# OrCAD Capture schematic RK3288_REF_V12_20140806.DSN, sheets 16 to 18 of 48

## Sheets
16 32.RAM-DDR3 2x32bit (option): size Custom; title: RAM-DDR3 2x32bit (option); note: RAM-DDR3 2x32bit (option)
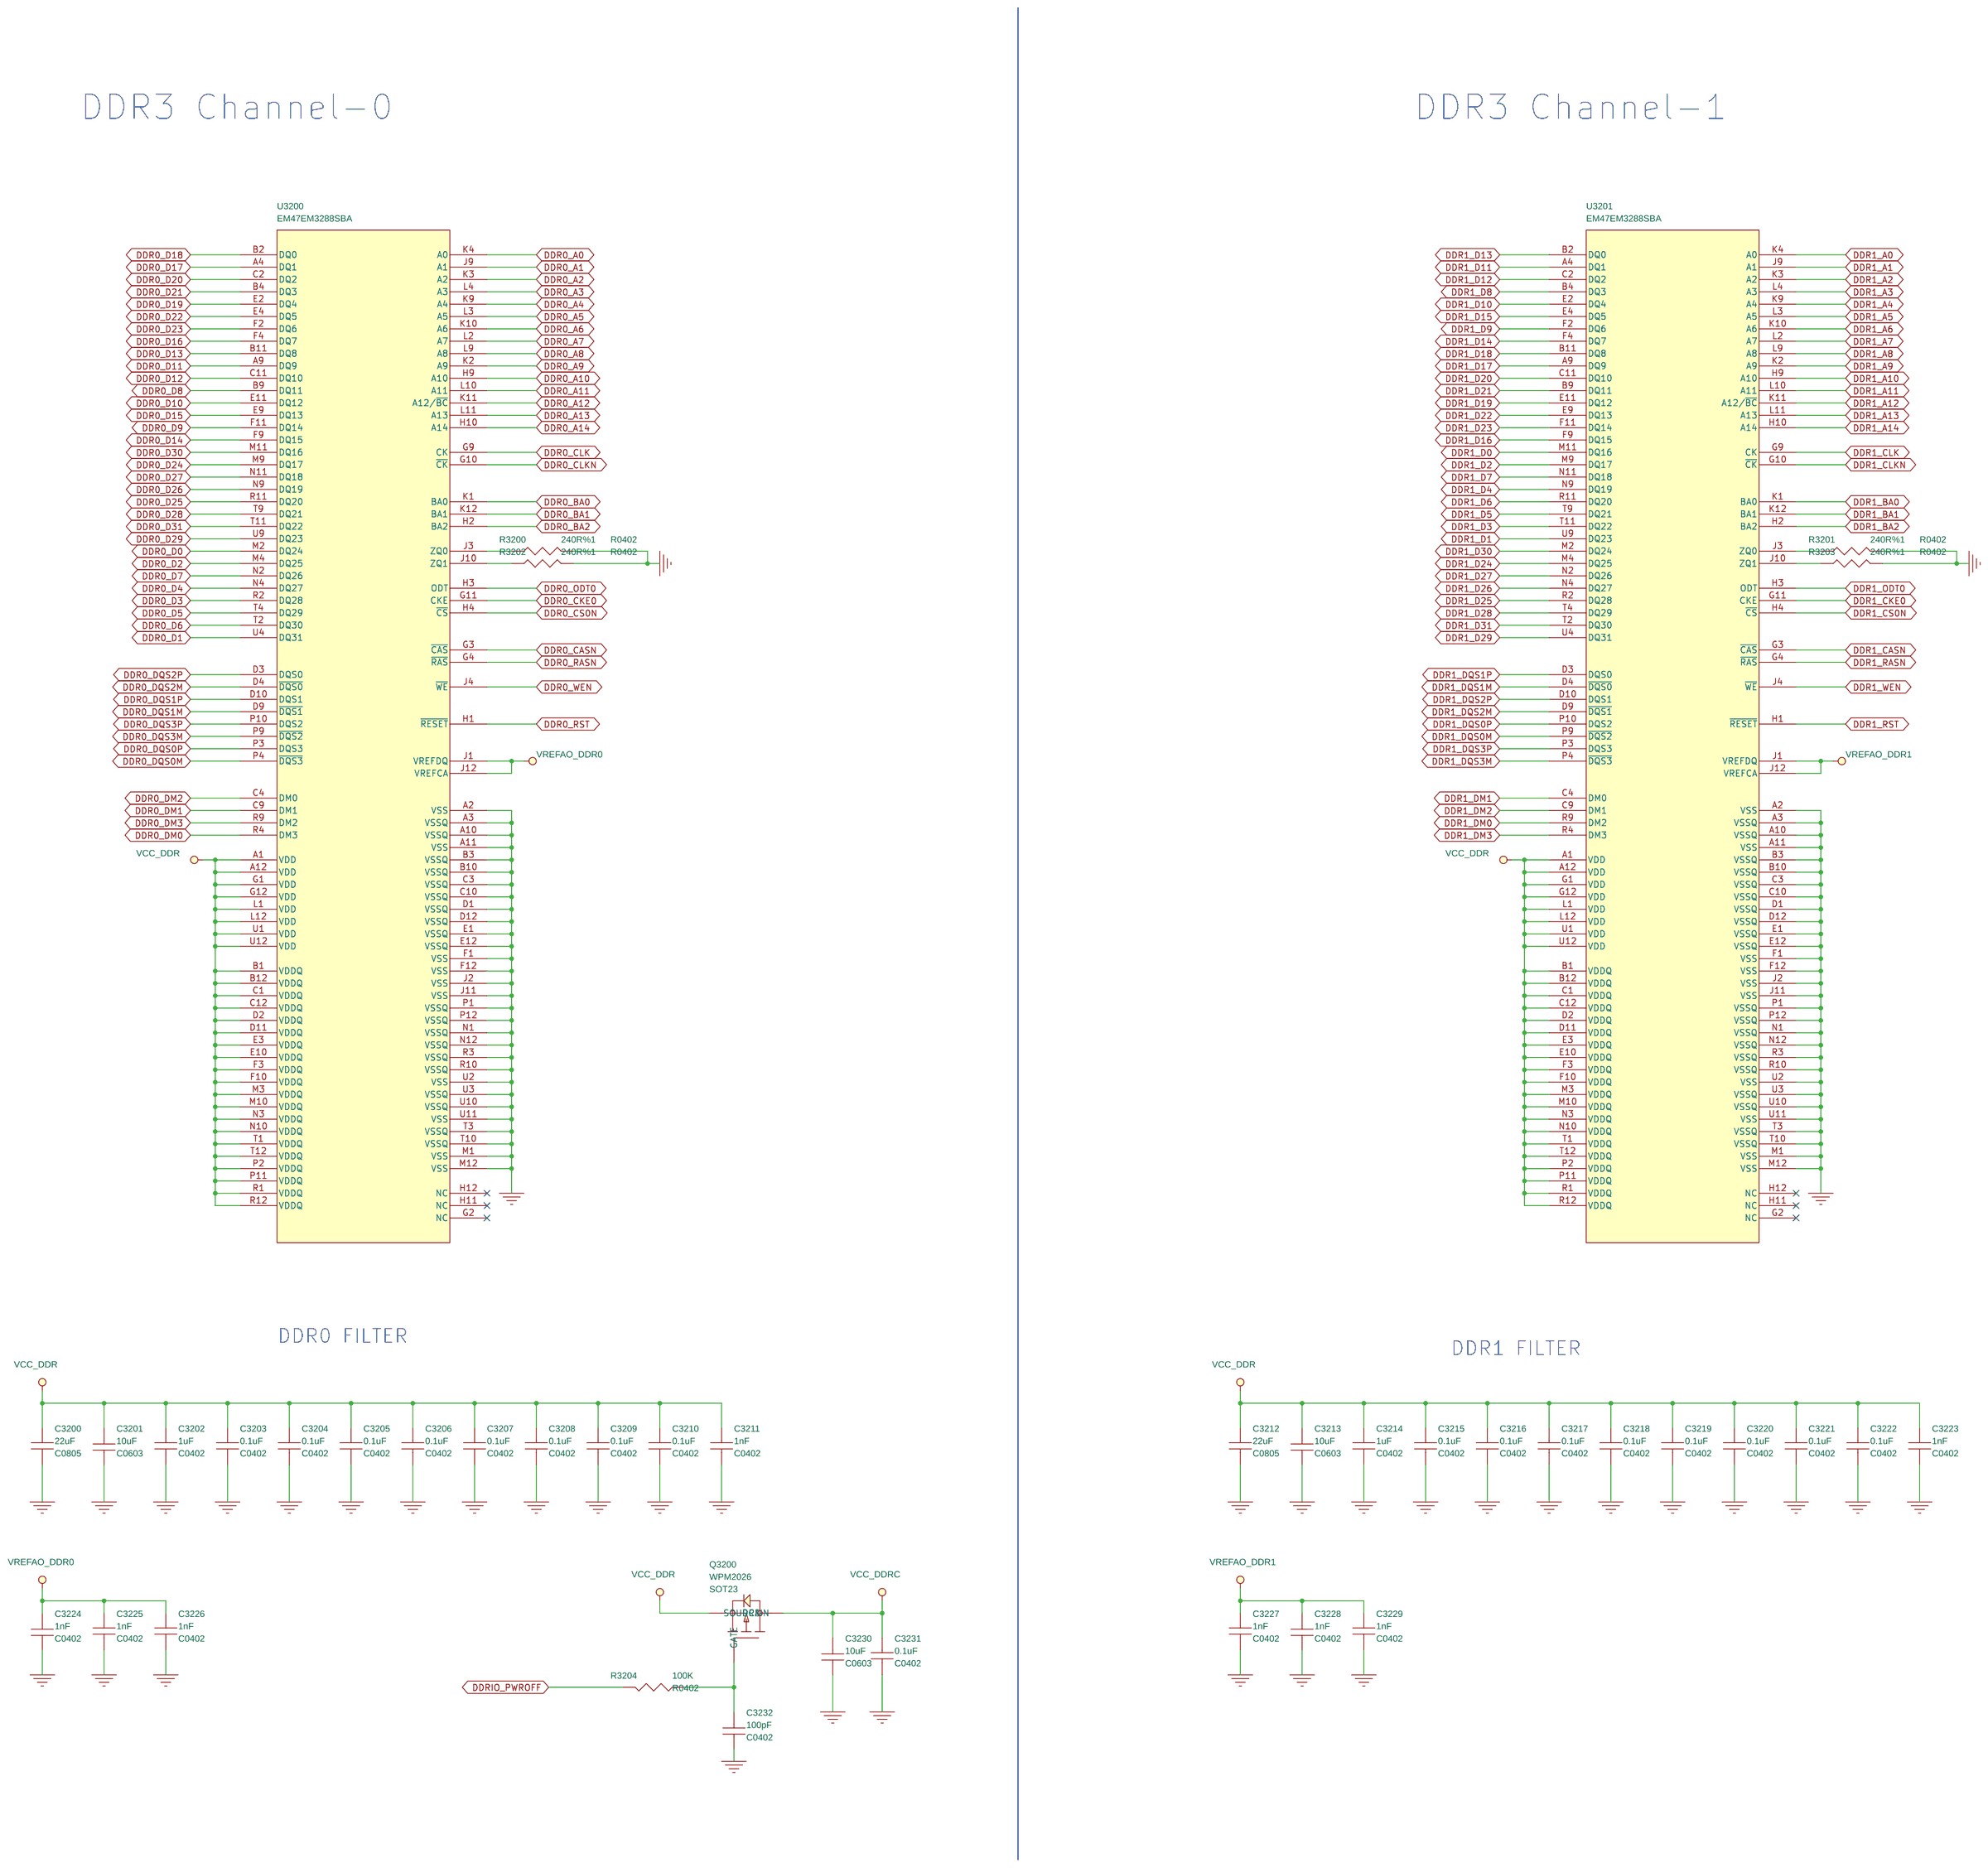
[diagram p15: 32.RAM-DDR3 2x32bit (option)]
17 33.RAM-LPDDR2(168P) (option): size Custom; title: RAM-LPDDR2(168P) (option); note: DDR-LPDDR2(168P) (option)
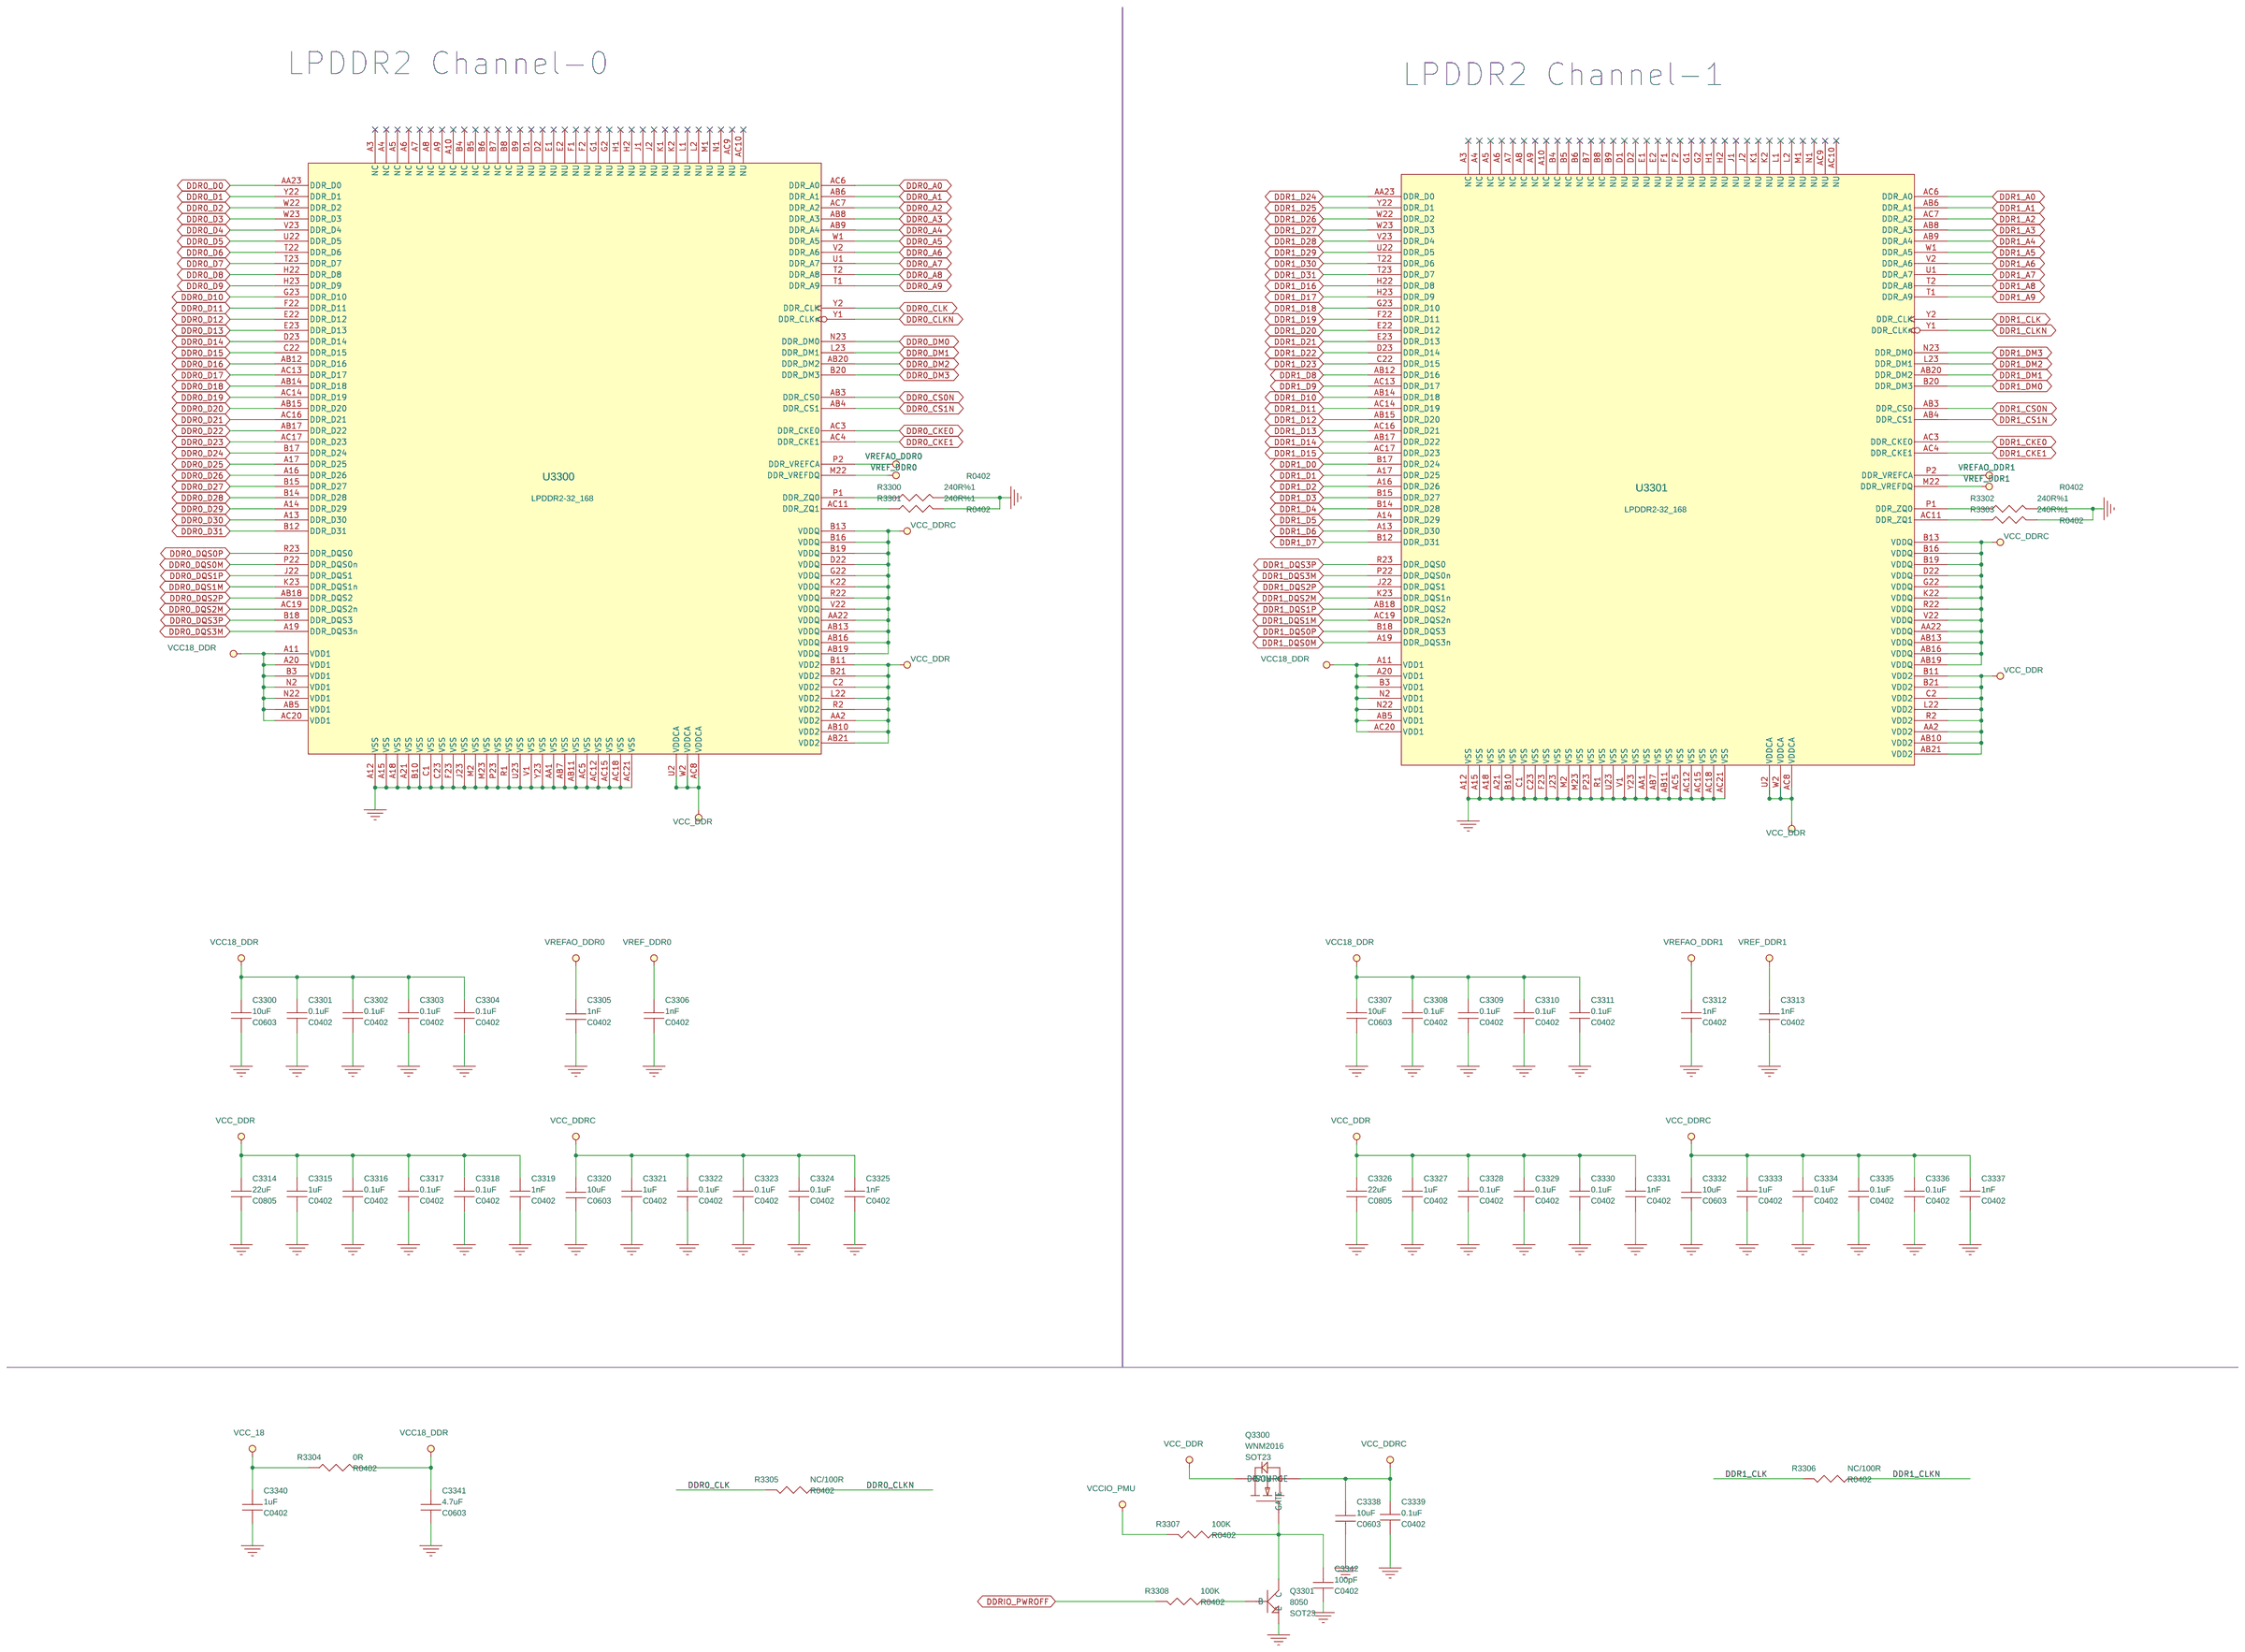
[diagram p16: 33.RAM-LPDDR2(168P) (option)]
18 34.RAM-LPDDR2(216P) (option): size A3; title: RAM-LPDDR2(216P) (option); note: DDR-LPDDR2(220P) (option)
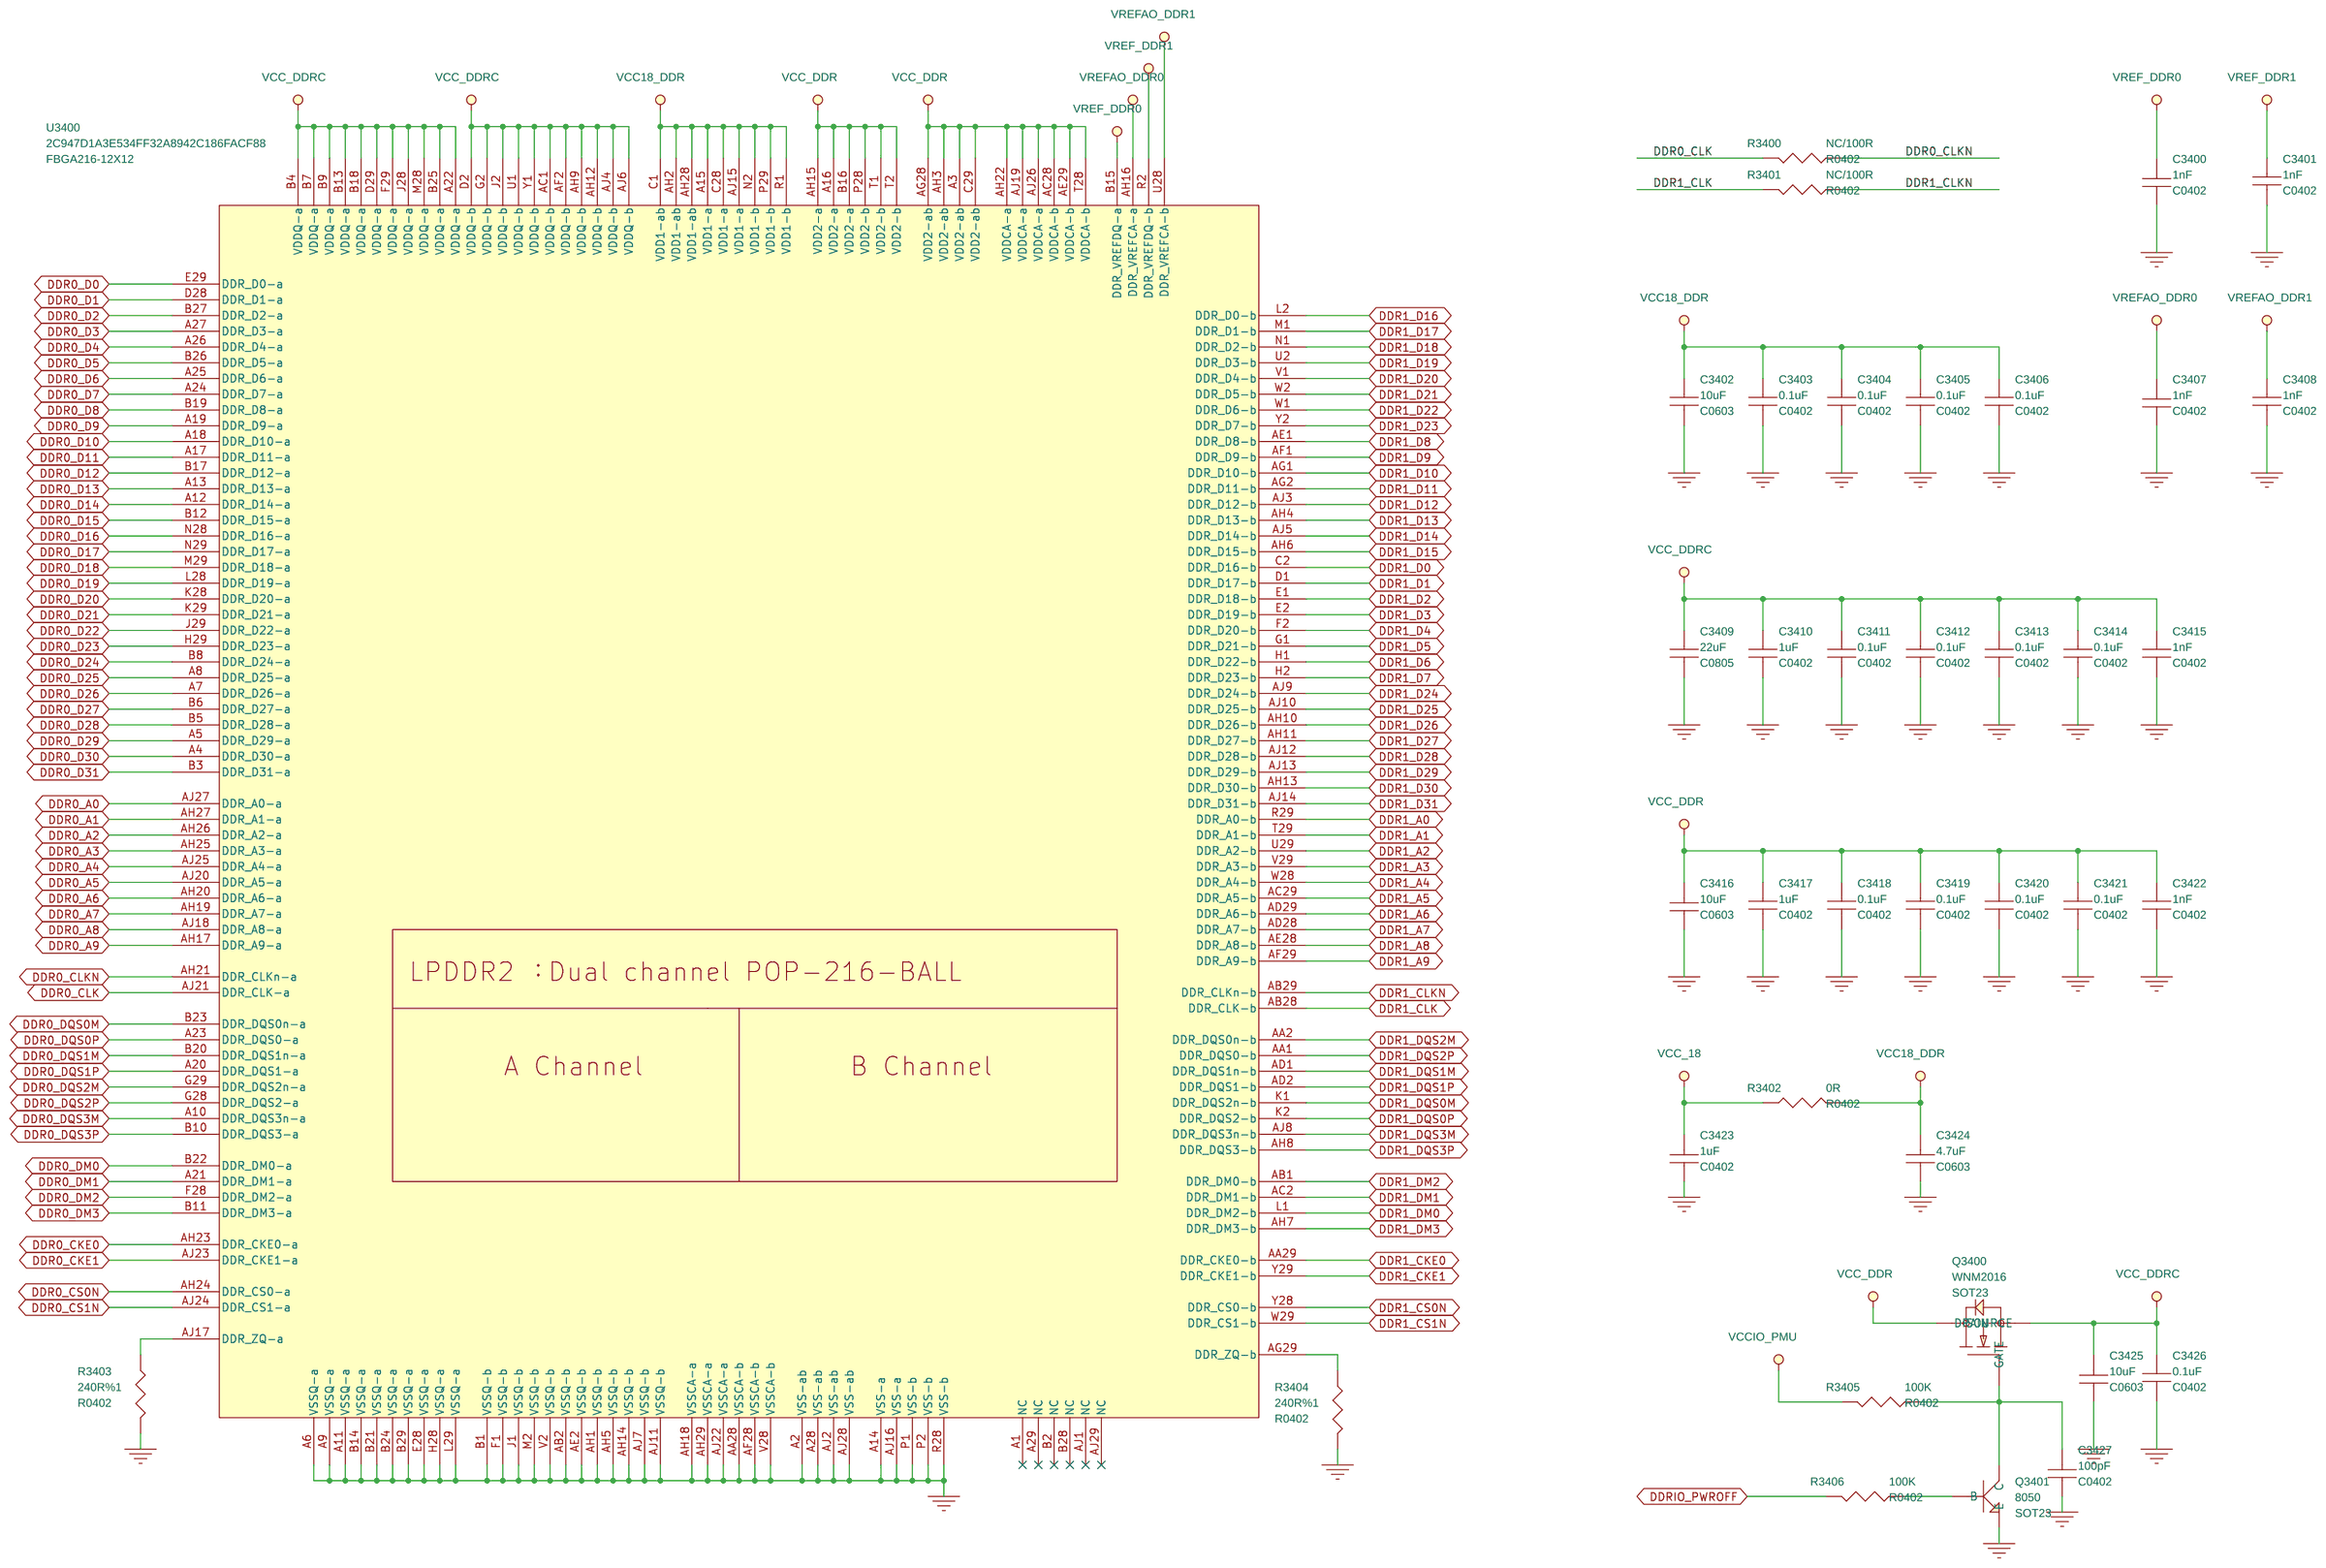
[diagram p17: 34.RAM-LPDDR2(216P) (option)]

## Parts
sheet 32.RAM-DDR3 2x32bit (option)
C3200  22uF  [C0805]
C3201  10uF  [C0603]
C3202  1uF  [C0402]
C3203  0.1uF  [C0402]
C3204  0.1uF  [C0402]
C3205  0.1uF  [C0402]
C3206  0.1uF  [C0402]
C3207  0.1uF  [C0402]
C3208  0.1uF  [C0402]
C3209  0.1uF  [C0402]
C3210  0.1uF  [C0402]
C3211  1nF  [C0402]
C3212  22uF  [C0805]
C3213  10uF  [C0603]
C3214  1uF  [C0402]
C3215  0.1uF  [C0402]
C3216  0.1uF  [C0402]
C3217  0.1uF  [C0402]
C3218  0.1uF  [C0402]
C3219  0.1uF  [C0402]
C3220  0.1uF  [C0402]
C3221  0.1uF  [C0402]
C3222  0.1uF  [C0402]
C3223  1nF  [C0402]
C3224  1nF  [C0402]
C3225  1nF  [C0402]
C3226  1nF  [C0402]
C3227  1nF  [C0402]
C3228  1nF  [C0402]
C3229  1nF  [C0402]
C3230  10uF  [C0603]
C3231  0.1uF  [C0402]
C3232  100pF  [C0402]
Q3200  WPM2026  [SOT23]
R3200  240R%1  [R0402]
R3201  240R%1  [R0402]
R3202  240R%1  [R0402]
R3203  240R%1  [R0402]
R3204  100K  [R0402]
U3200  EM47EM3288SBA  [136Ball-FBGA]
U3201  EM47EM3288SBA  [136Ball-FBGA]
sheet 33.RAM-LPDDR2(168P) (option)
C3300  10uF  [C0603]
C3301  0.1uF  [C0402]
C3302  0.1uF  [C0402]
C3303  0.1uF  [C0402]
C3304  0.1uF  [C0402]
C3305  1nF  [C0402]
C3306  1nF  [C0402]
C3307  10uF  [C0603]
C3308  0.1uF  [C0402]
C3309  0.1uF  [C0402]
C3310  0.1uF  [C0402]
C3311  0.1uF  [C0402]
C3312  1nF  [C0402]
C3313  1nF  [C0402]
C3314  22uF  [C0805]
C3315  1uF  [C0402]
C3316  0.1uF  [C0402]
C3317  0.1uF  [C0402]
C3318  0.1uF  [C0402]
C3319  1nF  [C0402]
C3320  10uF  [C0603]
C3321  1uF  [C0402]
C3322  0.1uF  [C0402]
C3323  0.1uF  [C0402]
C3324  0.1uF  [C0402]
C3325  1nF  [C0402]
C3326  22uF  [C0805]
C3327  1uF  [C0402]
C3328  0.1uF  [C0402]
C3329  0.1uF  [C0402]
C3330  0.1uF  [C0402]
C3331  1nF  [C0402]
C3332  10uF  [C0603]
C3333  1uF  [C0402]
C3334  0.1uF  [C0402]
C3335  0.1uF  [C0402]
C3336  0.1uF  [C0402]
C3337  1nF  [C0402]
C3338  10uF  [C0603]
C3339  0.1uF  [C0402]
C3340  1uF  [C0402]
C3341  4.7uF  [C0603]
C3342  100pF  [C0402]
Q3300  WNM2016  [SOT23]
Q3301  8050  [SOT23]
R3300  240R%1  [R0402]
R3301  240R%1  [R0402]
R3302  240R%1  [R0402]
R3303  240R%1  [R0402]
R3304  0R  [R0402]
R3305  NC/100R  [R0402]
R3306  NC/100R  [R0402]
R3307  100K  [R0402]
R3308  100K  [R0402]
U3300  LPDDR2-32_168  [FBGA168-12X12]
U3301  LPDDR2-32_168  [FBGA168-12X12]
sheet 34.RAM-LPDDR2(216P) (option)
C3400  1nF  [C0402]
C3401  1nF  [C0402]
C3402  10uF  [C0603]
C3403  0.1uF  [C0402]
C3404  0.1uF  [C0402]
C3405  0.1uF  [C0402]
C3406  0.1uF  [C0402]
C3407  1nF  [C0402]
C3408  1nF  [C0402]
C3409  22uF  [C0805]
C3410  1uF  [C0402]
C3411  0.1uF  [C0402]
C3412  0.1uF  [C0402]
C3413  0.1uF  [C0402]
C3414  0.1uF  [C0402]
C3415  1nF  [C0402]
C3416  10uF  [C0603]
C3417  1uF  [C0402]
C3418  0.1uF  [C0402]
C3419  0.1uF  [C0402]
C3420  0.1uF  [C0402]
C3421  0.1uF  [C0402]
C3422  1nF  [C0402]
C3423  1uF  [C0402]
C3424  4.7uF  [C0603]
C3425  10uF  [C0603]
C3426  0.1uF  [C0402]
C3427  100pF  [C0402]
Q3400  WNM2016  [SOT23]
Q3401  8050  [SOT23]
R3400  NC/100R  [R0402]
R3401  NC/100R  [R0402]
R3402  0R  [R0402]
R3403  240R%1  [R0402]
R3404  240R%1  [R0402]
R3405  100K  [R0402]
R3406  100K  [R0402]
U3400  2C947D1A3E534FF32A8942C186FACF88  [FBGA216-12X12]

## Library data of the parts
C3200-C3232 C3300-C3339 C3342 C3400-C3422 C3425-C3427 = CAP_NP
Q3200 = FET_P_MOS
R3200-R3203 R3300-R3306 R3400-R3404 = RESISTOR_0: 贴片电阻
R3204 R3307 R3308 R3405 R3406 = RESISTOR_0: RES,thick film,1MOhm,+/-5%,1/16W,SMD0402; MARK: 51K
U3200 U3201 = EM47EM3288SBA
C3340 C3341 C3423 C3424 = CAP_NP: CAP,MLCC,10uF,+/-10%,X5R,6.3V,SMD0805
Q3300 Q3400 = FET_N_MOS
Q3301 Q3401 = NPN4
U3300 U3301 = LPDDR2-32_3
U3400 = K3PE0E000E_1

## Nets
GND: C3200.2 C3201.1 C3202.2 C3203.2 C3204.2 C3205.2 C3206.2 C3207.2 C3208.2 C3209.2 C3210.2 C3211.2 C3212.2 C3213.1 C3214.2 C3215.2 C3216.2 C3217.2 C3218.2 C3219.2 C3220.2 C3221.2 C3222.2 C3223.2 C3224.1 C3225.2 C3226.2 C3227.2 C3228.1 C3229.2 C3230.1 C3231.2 C3232.1 C3300.2 C3301.2 C3302.2 C3303.2 C3304.2 C3305.1 C3306.2 C3307.2 C3308.2 C3309.2 C3310.2 C3311.2 C3312.2 C3313.1 C3314.2 C3315.2 C3316.2 C3317.2 C3318.2 C3319.2 C3320.1 C3321.2 C3322.2 C3323.2 C3324.2 C3325.2 C3326.2 C3327.2 C3328.2 C3329.2 C3330.2 C3331.2 C3332.1 C3333.2 C3334.2 C3335.2 C3336.2 C3337.2 C3338.1 C3339.2 C3340.1 C3341.1 C3342.1 C3400.1 C3401.2 C3402.2 C3403.2 C3404.2 C3405.2 C3406.2 C3407.1 C3408.2 C3409.2 C3410.2 C3411.2 C3412.2 C3413.2 C3414.2 C3415.2 C3416.1 C3417.2 C3418.2 C3419.2 C3420.2 C3421.2 C3422.2 C3423.1 C3424.1 C3425.1 C3426.2 C3427.1 Q3301.2(E) Q3401.2(E) R3200.2 R3201.2 R3202.2 R3203.2 R3300.2 R3301.2 R3302.2 R3303.2 R3403.2 R3404.2 U3200.A2(VSS) U3200.A3(VSSQ) U3200.A10(VSSQ) U3200.A11(VSS) U3200.B3(VSSQ) U3200.B10(VSSQ) U3200.C3(VSSQ) U3200.C10(VSSQ) U3200.D1(VSSQ) U3200.D12(VSSQ) U3200.E1(VSSQ) U3200.E12(VSSQ) U3200.F1(VSS) U3200.F12(VSS) U3200.J2(VSS) U3200.J11(VSS) U3200.M1(VSS) U3200.M12(VSS) U3200.N1(VSSQ) U3200.N12(VSSQ) U3200.P1(VSSQ) U3200.P12(VSSQ) U3200.R3(VSSQ) U3200.R10(VSSQ) U3200.T3(VSSQ) U3200.T10(VSSQ) U3200.U2(VSS) U3200.U3(VSSQ) U3200.U10(VSSQ) U3200.U11(VSS) U3201.A2(VSS) U3201.A3(VSSQ) U3201.A10(VSSQ) U3201.A11(VSS) U3201.B3(VSSQ) U3201.B10(VSSQ) U3201.C3(VSSQ) U3201.C10(VSSQ) U3201.D1(VSSQ) U3201.D12(VSSQ) U3201.E1(VSSQ) U3201.E12(VSSQ) U3201.F1(VSS) U3201.F12(VSS) U3201.J2(VSS) U3201.J11(VSS) U3201.M1(VSS) U3201.M12(VSS) U3201.N1(VSSQ) U3201.N12(VSSQ) U3201.P1(VSSQ) U3201.P12(VSSQ) U3201.R3(VSSQ) U3201.R10(VSSQ) U3201.T3(VSSQ) U3201.T10(VSSQ) U3201.U2(VSS) U3201.U3(VSSQ) U3201.U10(VSSQ) U3201.U11(VSS) U3300.A12(VSS) U3300.A15(VSS) U3300.A18(VSS) U3300.A21(VSS) U3300.AA1(VSS) U3300.AB7(VSS) U3300.AB11(VSS) U3300.AC5(VSS) U3300.AC12(VSS) U3300.AC15(VSS) U3300.AC18(VSS) U3300.AC21(VSS) U3300.B10(VSS) U3300.C1(VSS) U3300.C23(VSS) U3300.F23(VSS) U3300.J23(VSS) U3300.M2(VSS) U3300.M23(VSS) U3300.P23(VSS) U3300.R1(VSS) U3300.U23(VSS) U3300.V1(VSS) U3300.Y23(VSS) U3301.A12(VSS) U3301.A15(VSS) U3301.A18(VSS) U3301.A21(VSS) U3301.AA1(VSS) U3301.AB7(VSS) U3301.AB11(VSS) U3301.AC5(VSS) U3301.AC12(VSS) U3301.AC15(VSS) U3301.AC18(VSS) U3301.AC21(VSS) U3301.B10(VSS) U3301.C1(VSS) U3301.C23(VSS) U3301.F23(VSS) U3301.J23(VSS) U3301.M2(VSS) U3301.M23(VSS) U3301.P23(VSS) U3301.R1(VSS) U3301.U23(VSS) U3301.V1(VSS) U3301.Y23(VSS) U3400.A2(VSS-ab) U3400.A6(VSSQ-a) U3400.A9(VSSQ-a) U3400.A11(VSSQ-a) U3400.A14(VSS-a) U3400.A28(VSS-ab) U3400.AA28(VSSCA-b) U3400.AB2(VSSQ-b) U3400.AE2(VSSQ-b) U3400.AF28(VSSCA-b) U3400.AH1(VSSQ-b) U3400.AH5(VSSQ-b) U3400.AH14(VSSQ-b) U3400.AH18(VSSCA-a) U3400.AH29(VSSCA-a) U3400.AJ2(VSS-ab) U3400.AJ7(VSSQ-b) U3400.AJ11(VSSQ-b) U3400.AJ16(VSS-a) U3400.AJ22(VSSCA-a) U3400.AJ28(VSS-ab) U3400.B1(VSSQ-b) U3400.B14(VSSQ-a) U3400.B21(VSSQ-a) U3400.B24(VSSQ-a) U3400.B29(VSSQ-a) U3400.E28(VSSQ-a) U3400.F1(VSSQ-b) U3400.H28(VSSQ-a) U3400.J1(VSSQ-b) U3400.L29(VSSQ-a) U3400.M2(VSSQ-b) U3400.P1(VSS-b) U3400.P2(VSS-b) U3400.R28(VSS-b) U3400.V2(VSSQ-b) U3400.V28(VSSCA-b) ; also on sheet 5 6 7 8 9 10 11 12 13 14 15 19 20 21 22 23 24 25 26 27 28 29 30 31 32 33 34 35 36 37 38 39 40 41 42 43 44 45 46 47 48
VCC18_DDR: C3300.1 C3301.1 C3302.1 C3303.1 C3304.1 C3307.1 C3308.1 C3309.1 C3310.1 C3311.1 C3341.2 C3402.1 C3403.1 C3404.1 C3405.1 C3406.1 C3424.2 R3304.2 R3402.2 U3300.A11(VDD1) U3300.A20(VDD1) U3300.AB5(VDD1) U3300.AC20(VDD1) U3300.B3(VDD1) U3300.N2(VDD1) U3300.N22(VDD1) U3301.A11(VDD1) U3301.A20(VDD1) U3301.AB5(VDD1) U3301.AC20(VDD1) U3301.B3(VDD1) U3301.N2(VDD1) U3301.N22(VDD1) U3400.A15(VDD1-a) U3400.AH2(VDD1-ab) U3400.AH28(VDD1-ab) U3400.AJ15(VDD1-a) U3400.C1(VDD1-ab) U3400.C28(VDD1-a) U3400.N2(VDD1-b) U3400.P29(VDD1-b) U3400.R1(VDD1-b) ; also on sheet 19 20
VCC_18: C3340.2 C3423.2 R3304.1 R3402.1 ; also on sheet 13 14 19 20 32 33 34 35 45 46
VCC_DDR: C3200.1 C3201.2 C3202.1 C3203.1 C3204.1 C3205.1 C3206.1 C3207.1 C3208.1 C3209.1 C3210.1 C3211.1 C3212.1 C3213.2 C3214.1 C3215.1 C3216.1 C3217.1 C3218.1 C3219.1 C3220.1 C3221.1 C3222.1 C3223.1 C3314.1 C3315.1 C3316.1 C3317.1 C3318.1 C3319.1 C3326.1 C3327.1 C3328.1 C3329.1 C3330.1 C3331.1 C3416.2 C3417.1 C3418.1 C3419.1 C3420.1 C3421.1 C3422.1 Q3200.2(SOURCE) Q3300.3(DRAIN) Q3400.3(DRAIN) U3200.A1(VDD) U3200.A12(VDD) U3200.B1(VDDQ) U3200.B12(VDDQ) U3200.C1(VDDQ) U3200.C12(VDDQ) U3200.D2(VDDQ) U3200.D11(VDDQ) U3200.E3(VDDQ) U3200.E10(VDDQ) U3200.F3(VDDQ) U3200.F10(VDDQ) U3200.G1(VDD) U3200.G12(VDD) U3200.L1(VDD) U3200.L12(VDD) U3200.M3(VDDQ) U3200.M10(VDDQ) U3200.N3(VDDQ) U3200.N10(VDDQ) U3200.P2(VDDQ) U3200.P11(VDDQ) U3200.R1(VDDQ) U3200.R12(VDDQ) U3200.T1(VDDQ) U3200.T12(VDDQ) U3200.U1(VDD) U3200.U12(VDD) U3201.A1(VDD) U3201.A12(VDD) U3201.B1(VDDQ) U3201.B12(VDDQ) U3201.C1(VDDQ) U3201.C12(VDDQ) U3201.D2(VDDQ) U3201.D11(VDDQ) U3201.E3(VDDQ) U3201.E10(VDDQ) U3201.F3(VDDQ) U3201.F10(VDDQ) U3201.G1(VDD) U3201.G12(VDD) U3201.L1(VDD) U3201.L12(VDD) U3201.M3(VDDQ) U3201.M10(VDDQ) U3201.N3(VDDQ) U3201.N10(VDDQ) U3201.P2(VDDQ) U3201.P11(VDDQ) U3201.R1(VDDQ) U3201.R12(VDDQ) U3201.T1(VDDQ) U3201.T12(VDDQ) U3201.U1(VDD) U3201.U12(VDD) U3300.AA2(VDD2) U3300.AB10(VDD2) U3300.AB21(VDD2) U3300.AC8(VDDCA) U3300.B11(VDD2) U3300.B21(VDD2) U3300.C2(VDD2) U3300.L22(VDD2) U3300.R2(VDD2) U3300.U2(VDDCA) U3300.W2(VDDCA) U3301.AA2(VDD2) U3301.AB10(VDD2) U3301.AB21(VDD2) U3301.AC8(VDDCA) U3301.B11(VDD2) U3301.B21(VDD2) U3301.C2(VDD2) U3301.L22(VDD2) U3301.R2(VDD2) U3301.U2(VDDCA) U3301.W2(VDDCA) U3400.A3(VDD2-ab) U3400.A16(VDD2-a) U3400.AC28(VDDCA-b) U3400.AE29(VDDCA-b) U3400.AG28(VDD2-ab) U3400.AH3(VDD2-ab) U3400.AH15(VDD2-a) U3400.AH22(VDDCA-a) U3400.AJ19(VDDCA-a) U3400.AJ26(VDDCA-a) U3400.B16(VDD2-a) U3400.C29(VDD2-ab) U3400.P28(VDD2-b) U3400.T1(VDD2-b) U3400.T2(VDD2-b) U3400.T28(VDDCA-b) ; also on sheet 7 13 14 15 19 20
VCC_DDRC: C3230.2 C3231.1 C3320.2 C3321.1 C3322.1 C3323.1 C3324.1 C3325.1 C3332.2 C3333.1 C3334.1 C3335.1 C3336.1 C3337.1 C3338.2 C3339.1 C3409.1 C3410.1 C3411.1 C3412.1 C3413.1 C3414.1 C3415.1 C3425.2 C3426.1 Q3200.3(DRAIN) Q3300.2(SOURCE) Q3400.2(SOURCE) U3300.AA22(VDDQ) U3300.AB13(VDDQ) U3300.AB16(VDDQ) U3300.AB19(VDDQ) U3300.B13(VDDQ) U3300.B16(VDDQ) U3300.B19(VDDQ) U3300.D22(VDDQ) U3300.G22(VDDQ) U3300.K22(VDDQ) U3300.R22(VDDQ) U3300.V22(VDDQ) U3301.AA22(VDDQ) U3301.AB13(VDDQ) U3301.AB16(VDDQ) U3301.AB19(VDDQ) U3301.B13(VDDQ) U3301.B16(VDDQ) U3301.B19(VDDQ) U3301.D22(VDDQ) U3301.G22(VDDQ) U3301.K22(VDDQ) U3301.R22(VDDQ) U3301.V22(VDDQ) U3400.A22(VDDQ-a) U3400.AC1(VDDQ-b) U3400.AF2(VDDQ-b) U3400.AH9(VDDQ-b) U3400.AH12(VDDQ-b) U3400.AJ4(VDDQ-b) U3400.AJ6(VDDQ-b) U3400.B4(VDDQ-a) U3400.B7(VDDQ-a) U3400.B9(VDDQ-a) U3400.B13(VDDQ-a) U3400.B18(VDDQ-a) U3400.B25(VDDQ-a) U3400.D2(VDDQ-b) U3400.D29(VDDQ-a) U3400.F29(VDDQ-a) U3400.G2(VDDQ-b) U3400.J2(VDDQ-b) U3400.J28(VDDQ-a) U3400.M28(VDDQ-a) U3400.U1(VDDQ-b) U3400.Y1(VDDQ-b) ; also on sheet 7 15 19 20
VCCIO_PMU: R3307.2 R3405.2 ; also on sheet 6 11 13 14 19 20 24 33 34 35 41 43 46
DDR0_A0: U3200.K4(A0) U3300.AC6(DDR_A0) U3400.AJ27(DDR_A0-a) ; also on sheet 7 15 19 20
DDR0_A1: U3200.J9(A1) U3300.AB6(DDR_A1) U3400.AH27(DDR_A1-a) ; also on sheet 7 15 19 20
DDR0_A2: U3200.K3(A2) U3300.AC7(DDR_A2) U3400.AH26(DDR_A2-a) ; also on sheet 7 15 19 20
DDR0_A3: U3200.L4(A3) U3300.AB8(DDR_A3) U3400.AH25(DDR_A3-a) ; also on sheet 7 15 19 20
DDR0_A4: U3200.K9(A4) U3300.AB9(DDR_A4) U3400.AJ25(DDR_A4-a) ; also on sheet 7 15 19 20
DDR0_A5: U3200.L3(A5) U3300.W1(DDR_A5) U3400.AJ20(DDR_A5-a) ; also on sheet 7 15 19 20
DDR0_A6: U3200.K10(A6) U3300.V2(DDR_A6) U3400.AH20(DDR_A6-a) ; also on sheet 7 15 19 20
DDR0_A7: U3200.L2(A7) U3300.U1(DDR_A7) U3400.AH19(DDR_A7-a) ; also on sheet 7 15 19 20
DDR0_A8: U3200.L9(A8) U3300.T2(DDR_A8) U3400.AJ18(DDR_A8-a) ; also on sheet 7 15 19 20
DDR0_A9: U3200.K2(A9) U3300.T1(DDR_A9) U3400.AH17(DDR_A9-a) ; also on sheet 7 15 19 20
DDR0_A10: U3200.H9(A10) ; also on sheet 7 15
DDR0_A11: U3200.L10(A11) ; also on sheet 7 15
DDR0_A12: U3200.K11(A12/~{BC}) ; also on sheet 7 15
DDR0_A13: U3200.L11(A13) ; also on sheet 7 15
DDR0_A14: U3200.H10(A14) ; also on sheet 7 15
DDR0_BA0: U3200.K1(BA0) ; also on sheet 7 15
DDR0_BA1: U3200.K12(BA1) ; also on sheet 7 15
DDR0_BA2: U3200.H2(BA2) ; also on sheet 7 15
DDR0_CASN: U3200.G3(~{CAS}) ; also on sheet 7 15
DDR0_CKE0: U3200.G11(CKE) U3300.AC3(DDR_CKE0) U3400.AH23(DDR_CKE0-a) ; also on sheet 7 15 19 20
DDR0_CKE1: U3300.AC4(DDR_CKE1) U3400.AJ23(DDR_CKE1-a) ; also on sheet 7 15 19 20
DDR0_CLK: R3305.2 R3400.2 U3200.G9(CK) U3300.Y2(DDR_CLK) U3400.AJ21(DDR_CLK-a) ; also on sheet 7 15 19 20
DDR0_CLKN: R3305.1 R3400.1 U3200.G10(~{CK}) U3300.Y1(DDR_CLKn) U3400.AH21(DDR_CLKn-a) ; also on sheet 7 15 19 20
DDR0_CS0N: U3200.H4(~{CS}) U3300.AB3(DDR_CS0) U3400.AH24(DDR_CS0-a) ; also on sheet 7 15 19 20
DDR0_CS1N: U3300.AB4(DDR_CS1) U3400.AJ24(DDR_CS1-a) ; also on sheet 7 15 19 20
DDR0_D0: U3200.M2(DQ24) U3300.AA23(DDR_D0) U3400.E29(DDR_D0-a) ; also on sheet 7 15 19 20
DDR0_D1: U3200.U4(DQ31) U3300.Y22(DDR_D1) U3400.D28(DDR_D1-a) ; also on sheet 7 15 19 20
DDR0_D2: U3200.M4(DQ25) U3300.W22(DDR_D2) U3400.B27(DDR_D2-a) ; also on sheet 7 15 19 20
DDR0_D3: U3200.R2(DQ28) U3300.W23(DDR_D3) U3400.A27(DDR_D3-a) ; also on sheet 7 15 19 20
DDR0_D4: U3200.N4(DQ27) U3300.V23(DDR_D4) U3400.A26(DDR_D4-a) ; also on sheet 7 15 19 20
DDR0_D5: U3200.T4(DQ29) U3300.U22(DDR_D5) U3400.B26(DDR_D5-a) ; also on sheet 7 15 19 20
DDR0_D6: U3200.T2(DQ30) U3300.T22(DDR_D6) U3400.A25(DDR_D6-a) ; also on sheet 7 15 19 20
DDR0_D7: U3200.N2(DQ26) U3300.T23(DDR_D7) U3400.A24(DDR_D7-a) ; also on sheet 7 15 19 20
DDR0_D8: U3200.B9(DQ11) U3300.H22(DDR_D8) U3400.B19(DDR_D8-a) ; also on sheet 7 15 19 20
DDR0_D9: U3200.F11(DQ14) U3300.H23(DDR_D9) U3400.A19(DDR_D9-a) ; also on sheet 7 15 19 20
DDR0_D10: U3200.E11(DQ12) U3300.G23(DDR_D10) U3400.A18(DDR_D10-a) ; also on sheet 7 15 19 20
DDR0_D11: U3200.A9(DQ9) U3300.F22(DDR_D11) U3400.A17(DDR_D11-a) ; also on sheet 7 15 19 20
DDR0_D12: U3200.C11(DQ10) U3300.E22(DDR_D12) U3400.B17(DDR_D12-a) ; also on sheet 7 15 19 20
DDR0_D13: U3200.B11(DQ8) U3300.E23(DDR_D13) U3400.A13(DDR_D13-a) ; also on sheet 7 15 19 20
DDR0_D14: U3200.F9(DQ15) U3300.D23(DDR_D14) U3400.A12(DDR_D14-a) ; also on sheet 7 15 19 20
DDR0_D15: U3200.E9(DQ13) U3300.C22(DDR_D15) U3400.B12(DDR_D15-a) ; also on sheet 7 15 19 20
DDR0_D16: U3200.F4(DQ7) U3300.AB12(DDR_D16) U3400.N28(DDR_D16-a) ; also on sheet 7 15 19 20
DDR0_D17: U3200.A4(DQ1) U3300.AC13(DDR_D17) U3400.N29(DDR_D17-a) ; also on sheet 7 15 19 20
DDR0_D18: U3200.B2(DQ0) U3300.AB14(DDR_D18) U3400.M29(DDR_D18-a) ; also on sheet 7 15 19 20
DDR0_D19: U3200.E2(DQ4) U3300.AC14(DDR_D19) U3400.L28(DDR_D19-a) ; also on sheet 7 15 19 20
DDR0_D20: U3200.C2(DQ2) U3300.AB15(DDR_D20) U3400.K28(DDR_D20-a) ; also on sheet 7 15 19 20
DDR0_D21: U3200.B4(DQ3) U3300.AC16(DDR_D21) U3400.K29(DDR_D21-a) ; also on sheet 7 15 19 20
DDR0_D22: U3200.E4(DQ5) U3300.AB17(DDR_D22) U3400.J29(DDR_D22-a) ; also on sheet 7 15 19 20
DDR0_D23: U3200.F2(DQ6) U3300.AC17(DDR_D23) U3400.H29(DDR_D23-a) ; also on sheet 7 15 19 20
DDR0_D24: U3200.M9(DQ17) U3300.B17(DDR_D24) U3400.B8(DDR_D24-a) ; also on sheet 7 15 19 20
DDR0_D25: U3200.R11(DQ20) U3300.A17(DDR_D25) U3400.A8(DDR_D25-a) ; also on sheet 7 15 19 20
DDR0_D26: U3200.N9(DQ19) U3300.A16(DDR_D26) U3400.A7(DDR_D26-a) ; also on sheet 7 15 19 20
DDR0_D27: U3200.N11(DQ18) U3300.B15(DDR_D27) U3400.B6(DDR_D27-a) ; also on sheet 7 15 19 20
DDR0_D28: U3200.T9(DQ21) U3300.B14(DDR_D28) U3400.B5(DDR_D28-a) ; also on sheet 7 15 19 20
DDR0_D29: U3200.U9(DQ23) U3300.A14(DDR_D29) U3400.A5(DDR_D29-a) ; also on sheet 7 15 19 20
DDR0_D30: U3200.M11(DQ16) U3300.A13(DDR_D30) U3400.A4(DDR_D30-a) ; also on sheet 7 15 19 20
DDR0_D31: U3200.T11(DQ22) U3300.B12(DDR_D31) U3400.B3(DDR_D31-a) ; also on sheet 7 15 19 20
DDR0_DM0: U3200.R4(DM3) U3300.N23(DDR_DM0) U3400.B22(DDR_DM0-a) ; also on sheet 7 15 19 20
DDR0_DM1: U3200.C9(DM1) U3300.L23(DDR_DM1) U3400.A21(DDR_DM1-a) ; also on sheet 7 15 19 20
DDR0_DM2: U3200.C4(DM0) U3300.AB20(DDR_DM2) U3400.F28(DDR_DM2-a) ; also on sheet 7 15 19 20
DDR0_DM3: U3200.R9(DM2) U3300.B20(DDR_DM3) U3400.B11(DDR_DM3-a) ; also on sheet 7 15 19 20
DDR0_DQS0M: U3200.P4(~{DQS3}) U3300.P22(DDR_DQS0n) U3400.B23(DDR_DQS0n-a) ; also on sheet 7 15 19 20
DDR0_DQS0P: U3200.P3(DQS3) U3300.R23(DDR_DQS0) U3400.A23(DDR_DQS0-a) ; also on sheet 7 15 19 20
DDR0_DQS1M: U3200.D9(~{DQS1}) U3300.K23(DDR_DQS1n) U3400.B20(DDR_DQS1n-a) ; also on sheet 7 15 19 20
DDR0_DQS1P: U3200.D10(DQS1) U3300.J22(DDR_DQS1) U3400.A20(DDR_DQS1-a) ; also on sheet 7 15 19 20
DDR0_DQS2M: U3200.D4(~{DQS0}) U3300.AC19(DDR_DQS2n) U3400.G29(DDR_DQS2n-a) ; also on sheet 7 15 19 20
DDR0_DQS2P: U3200.D3(DQS0) U3300.AB18(DDR_DQS2) U3400.G28(DDR_DQS2-a) ; also on sheet 7 15 19 20
DDR0_DQS3M: U3200.P9(~{DQS2}) U3300.A19(DDR_DQS3n) U3400.A10(DDR_DQS3n-a) ; also on sheet 7 15 19 20
DDR0_DQS3P: U3200.P10(DQS2) U3300.B18(DDR_DQS3) U3400.B10(DDR_DQS3-a) ; also on sheet 7 15 19 20
DDR0_ODT0: U3200.H3(ODT) ; also on sheet 7 15 20
DDR0_RASN: U3200.G4(~{RAS}) ; also on sheet 7 15
DDR0_RST: U3200.H1(~{RESET}) ; also on sheet 7 15
DDR0_WEN: U3200.J4(~{WE}) ; also on sheet 7 15
DDR1_A0: U3201.K4(A0) U3301.AC6(DDR_A0) U3400.R29(DDR_A0-b) ; also on sheet 7 15 19 20
DDR1_A1: U3201.J9(A1) U3301.AB6(DDR_A1) U3400.T29(DDR_A1-b) ; also on sheet 7 15 19 20
DDR1_A2: U3201.K3(A2) U3301.AC7(DDR_A2) U3400.U29(DDR_A2-b) ; also on sheet 7 15 19 20
DDR1_A3: U3201.L4(A3) U3301.AB8(DDR_A3) U3400.V29(DDR_A3-b) ; also on sheet 7 15 19 20
DDR1_A4: U3201.K9(A4) U3301.AB9(DDR_A4) U3400.W28(DDR_A4-b) ; also on sheet 7 15 19 20
DDR1_A5: U3201.L3(A5) U3301.W1(DDR_A5) U3400.AC29(DDR_A5-b) ; also on sheet 7 15 19 20
DDR1_A6: U3201.K10(A6) U3301.V2(DDR_A6) U3400.AD29(DDR_A6-b) ; also on sheet 7 15 19 20
DDR1_A7: U3201.L2(A7) U3301.U1(DDR_A7) U3400.AD28(DDR_A7-b) ; also on sheet 7 15 19 20
DDR1_A8: U3201.L9(A8) U3301.T2(DDR_A8) U3400.AE28(DDR_A8-b) ; also on sheet 7 15 19 20
DDR1_A9: U3201.K2(A9) U3301.T1(DDR_A9) U3400.AF29(DDR_A9-b) ; also on sheet 7 15 19 20
DDR1_A10: U3201.H9(A10) ; also on sheet 7 15
DDR1_A11: U3201.L10(A11) ; also on sheet 7 15
DDR1_A12: U3201.K11(A12/~{BC}) ; also on sheet 7 15
DDR1_A13: U3201.L11(A13) ; also on sheet 7 15
DDR1_A14: U3201.H10(A14) ; also on sheet 7 15
DDR1_BA0: U3201.K1(BA0) ; also on sheet 7 15
DDR1_BA1: U3201.K12(BA1) ; also on sheet 7 15
DDR1_BA2: U3201.H2(BA2) ; also on sheet 7 15
DDR1_CASN: U3201.G3(~{CAS}) ; also on sheet 7 15
DDR1_CKE0: U3201.G11(CKE) U3301.AC3(DDR_CKE0) U3400.AA29(DDR_CKE0-b) ; also on sheet 7 15 19 20
DDR1_CKE1: U3301.AC4(DDR_CKE1) U3400.Y29(DDR_CKE1-b) ; also on sheet 7 15 19 20
DDR1_CLK: R3306.2 R3401.2 U3201.G9(CK) U3301.Y2(DDR_CLK) U3400.AB28(DDR_CLK-b) ; also on sheet 7 15 19 20
DDR1_CLKN: R3306.1 R3401.1 U3201.G10(~{CK}) U3301.Y1(DDR_CLKn) U3400.AB29(DDR_CLKn-b) ; also on sheet 7 15 19 20
DDR1_CS0N: U3201.H4(~{CS}) U3301.AB3(DDR_CS0) U3400.Y28(DDR_CS0-b) ; also on sheet 7 15 19 20
DDR1_CS1N: U3301.AB4(DDR_CS1) U3400.W29(DDR_CS1-b) ; also on sheet 7 15 19 20
DDR1_D0: U3201.M11(DQ16) U3301.B17(DDR_D24) U3400.C2(DDR_D16-b) ; also on sheet 7 15 19 20
DDR1_D1: U3201.U9(DQ23) U3301.A17(DDR_D25) U3400.D1(DDR_D17-b) ; also on sheet 7 15 19 20
DDR1_D2: U3201.M9(DQ17) U3301.A16(DDR_D26) U3400.E1(DDR_D18-b) ; also on sheet 7 15 19 20
DDR1_D3: U3201.T11(DQ22) U3301.B15(DDR_D27) U3400.E2(DDR_D19-b) ; also on sheet 7 15 19 20
DDR1_D4: U3201.N9(DQ19) U3301.B14(DDR_D28) U3400.F2(DDR_D20-b) ; also on sheet 7 15 19 20
DDR1_D5: U3201.T9(DQ21) U3301.A14(DDR_D29) U3400.G1(DDR_D21-b) ; also on sheet 7 15 19 20
DDR1_D6: U3201.R11(DQ20) U3301.A13(DDR_D30) U3400.H1(DDR_D22-b) ; also on sheet 7 15 19 20
DDR1_D7: U3201.N11(DQ18) U3301.B12(DDR_D31) U3400.H2(DDR_D23-b) ; also on sheet 7 15 19 20
DDR1_D8: U3201.B4(DQ3) U3301.AB12(DDR_D16) U3400.AE1(DDR_D8-b) ; also on sheet 7 15 19 20
DDR1_D9: U3201.F2(DQ6) U3301.AC13(DDR_D17) U3400.AF1(DDR_D9-b) ; also on sheet 7 15 19 20
DDR1_D10: U3201.E2(DQ4) U3301.AB14(DDR_D18) U3400.AG1(DDR_D10-b) ; also on sheet 7 15 19 20
DDR1_D11: U3201.A4(DQ1) U3301.AC14(DDR_D19) U3400.AG2(DDR_D11-b) ; also on sheet 7 15 19 20
DDR1_D12: U3201.C2(DQ2) U3301.AB15(DDR_D20) U3400.AJ3(DDR_D12-b) ; also on sheet 7 15 19 20
DDR1_D13: U3201.B2(DQ0) U3301.AC16(DDR_D21) U3400.AH4(DDR_D13-b) ; also on sheet 7 15 19 20
DDR1_D14: U3201.F4(DQ7) U3301.AB17(DDR_D22) U3400.AJ5(DDR_D14-b) ; also on sheet 7 15 19 20
DDR1_D15: U3201.E4(DQ5) U3301.AC17(DDR_D23) U3400.AH6(DDR_D15-b) ; also on sheet 7 15 19 20
DDR1_D16: U3201.F9(DQ15) U3301.H22(DDR_D8) U3400.L2(DDR_D0-b) ; also on sheet 7 15 19 20
DDR1_D17: U3201.A9(DQ9) U3301.H23(DDR_D9) U3400.M1(DDR_D1-b) ; also on sheet 7 15 19 20
DDR1_D18: U3201.B11(DQ8) U3301.G23(DDR_D10) U3400.N1(DDR_D2-b) ; also on sheet 7 15 19 20
DDR1_D19: U3201.E11(DQ12) U3301.F22(DDR_D11) U3400.U2(DDR_D3-b) ; also on sheet 7 15 19 20
DDR1_D20: U3201.C11(DQ10) U3301.E22(DDR_D12) U3400.V1(DDR_D4-b) ; also on sheet 7 15 19 20
DDR1_D21: U3201.B9(DQ11) U3301.E23(DDR_D13) U3400.W2(DDR_D5-b) ; also on sheet 7 15 19 20
DDR1_D22: U3201.E9(DQ13) U3301.D23(DDR_D14) U3400.W1(DDR_D6-b) ; also on sheet 7 15 19 20
DDR1_D23: U3201.F11(DQ14) U3301.C22(DDR_D15) U3400.Y2(DDR_D7-b) ; also on sheet 7 15 19 20
DDR1_D24: U3201.M4(DQ25) U3301.AA23(DDR_D0) U3400.AJ9(DDR_D24-b) ; also on sheet 7 15 19 20
DDR1_D25: U3201.R2(DQ28) U3301.Y22(DDR_D1) U3400.AJ10(DDR_D25-b) ; also on sheet 7 15 19 20
DDR1_D26: U3201.N4(DQ27) U3301.W22(DDR_D2) U3400.AH10(DDR_D26-b) ; also on sheet 7 15 19 20
DDR1_D27: U3201.N2(DQ26) U3301.W23(DDR_D3) U3400.AH11(DDR_D27-b) ; also on sheet 7 15 19 20
DDR1_D28: U3201.T4(DQ29) U3301.V23(DDR_D4) U3400.AJ12(DDR_D28-b) ; also on sheet 7 15 19 20
DDR1_D29: U3201.U4(DQ31) U3301.U22(DDR_D5) U3400.AJ13(DDR_D29-b) ; also on sheet 7 15 19 20
DDR1_D30: U3201.M2(DQ24) U3301.T22(DDR_D6) U3400.AH13(DDR_D30-b) ; also on sheet 7 15 19 20
DDR1_D31: U3201.T2(DQ30) U3301.T23(DDR_D7) U3400.AJ14(DDR_D31-b) ; also on sheet 7 15 19 20
DDR1_DM0: U3201.R9(DM2) U3301.B20(DDR_DM3) U3400.L1(DDR_DM2-b) ; also on sheet 7 15 19 20
DDR1_DM1: U3201.C4(DM0) U3301.AB20(DDR_DM2) U3400.AC2(DDR_DM1-b) ; also on sheet 7 15 19 20
DDR1_DM2: U3201.C9(DM1) U3301.L23(DDR_DM1) U3400.AB1(DDR_DM0-b) ; also on sheet 7 15 19 20
DDR1_DM3: U3201.R4(DM3) U3301.N23(DDR_DM0) U3400.AH7(DDR_DM3-b) ; also on sheet 7 15 19 20
DDR1_DQS0M: U3201.P9(~{DQS2}) U3301.A19(DDR_DQS3n) U3400.K1(DDR_DQS2n-b) ; also on sheet 7 15 19 20
DDR1_DQS0P: U3201.P10(DQS2) U3301.B18(DDR_DQS3) U3400.K2(DDR_DQS2-b) ; also on sheet 7 15 19 20
DDR1_DQS1M: U3201.D4(~{DQS0}) U3301.AC19(DDR_DQS2n) U3400.AD1(DDR_DQS1n-b) ; also on sheet 7 15 19 20
DDR1_DQS1P: U3201.D3(DQS0) U3301.AB18(DDR_DQS2) U3400.AD2(DDR_DQS1-b) ; also on sheet 7 15 19 20
DDR1_DQS2M: U3201.D9(~{DQS1}) U3301.K23(DDR_DQS1n) U3400.AA2(DDR_DQS0n-b) ; also on sheet 7 15 19 20
DDR1_DQS2P: U3201.D10(DQS1) U3301.J22(DDR_DQS1) U3400.AA1(DDR_DQS0-b) ; also on sheet 7 15 19 20
DDR1_DQS3M: U3201.P4(~{DQS3}) U3301.P22(DDR_DQS0n) U3400.AJ8(DDR_DQS3n-b) ; also on sheet 7 15 19 20
DDR1_DQS3P: U3201.P3(DQS3) U3301.R23(DDR_DQS0) U3400.AH8(DDR_DQS3-b) ; also on sheet 7 15 19 20
DDR1_ODT0: U3201.H3(ODT) ; also on sheet 7 15 20
DDR1_RASN: U3201.G4(~{RAS}) ; also on sheet 7 15
DDR1_RST: U3201.H1(~{RESET}) ; also on sheet 7 15
DDR1_WEN: U3201.J4(~{WE}) ; also on sheet 7 15
DDRIO_PWROFF: R3204.2 R3308.2 R3406.2 ; also on sheet 6 15 19 20
VREF_DDR0: C3306.1 C3400.2 U3300.M22(DDR_VREFDQ) U3400.B15(DDR_VREFDQ-a) ; also on sheet 7 19 20
VREF_DDR1: C3313.2 C3401.1 U3301.M22(DDR_VREFDQ) U3400.R2(DDR_VREFDQ-b) ; also on sheet 7 19 20
VREFAO_DDR0: C3224.2 C3225.1 C3226.1 C3305.2 C3407.2 U3200.J1(VREFDQ) U3200.J12(VREFCA) U3300.P2(DDR_VREFCA) U3400.AH16(DDR_VREFCA-a) ; also on sheet 7 15 19 20
VREFAO_DDR1: C3227.1 C3228.2 C3229.1 C3312.1 C3408.1 U3201.J1(VREFDQ) U3201.J12(VREFCA) U3301.P2(DDR_VREFCA) U3400.U28(DDR_VREFCA-b) ; also on sheet 7 15 19 20
N61267029: R3301.1 U3300.AC11(DDR_ZQ1)
N61267297: R3303.1 U3301.AC11(DDR_ZQ1)
N61267379: R3302.1 U3301.P1(DDR_ZQ0)
N61267380: R3300.1 U3300.P1(DDR_ZQ0)
N61745312: R3403.1 U3400.AJ17(DDR_ZQ-a)
N61802819: R3200.1 U3200.J3(ZQ0)
N61802821: R3202.1 U3200.J10(ZQ1)
N61804538: R3203.1 U3201.J10(ZQ1)
N61804540: R3201.1 U3201.J3(ZQ0)
N62662862: C3427.2 Q3400.1(GATE) Q3401.3(C) R3405.1
N62662864: Q3401.1(B) R3406.1
N62663387: C3342.2 Q3300.1(GATE) Q3301.3(C) R3307.1
N62663389: Q3301.1(B) R3308.1
N62670596: C3232.2 Q3200.1(GATE) R3204.1
N63666242: R3404.1 U3400.AG29(DDR_ZQ-b)

Not connected (* = marked no-connect by the designer): U3200 G2(NC)* H11(NC)* H12(NC)*; U3201 G2(NC)* H11(NC)* H12(NC)*; U3300 A3(NC)* A4(NC)* A5(NC)* A6(NC)* A7(NC)* A8(NC)* A9(NC)* A10(NC)* AC9(NU)* AC10(NU)* B4(NC)* B5(NC)* B6(NC)* B7(NC)* B8(NC)* B9(NU)* D1(NU)* D2(NU)* E1(NU)* E2(NU)* F1(NU)* F2(NU)* G1(NU)* G2(NU)* H1(NU)* H2(NU)* J1(NU)* J2(NU)* K1(NU)* K2(NU)* L1(NU)* L2(NU)* M1(NU)* N1(NU)*; U3301 A3(NC)* A4(NC)* A5(NC)* A6(NC)* A7(NC)* A8(NC)* A9(NC)* A10(NC)* AC9(NU)* AC10(NU)* B4(NC)* B5(NC)* B6(NC)* B7(NC)* B8(NC)* B9(NU)* D1(NU)* D2(NU)* E1(NU)* E2(NU)* F1(NU)* F2(NU)* G1(NU)* G2(NU)* H1(NU)* H2(NU)* J1(NU)* J2(NU)* K1(NU)* K2(NU)* L1(NU)* L2(NU)* M1(NU)* N1(NU)*; U3400 A1(NC)* A29(NC)* AJ1(NC)* AJ29(NC)* B2(NC)* B28(NC)*

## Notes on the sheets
sheet 16
- DDR3 Channel-0
- DDR3 Channel-1
- DDR0 FILTER
- DDR1 FILTER
sheet 17
- LPDDR2 Channel-0
- LPDDR2 Channel-1
